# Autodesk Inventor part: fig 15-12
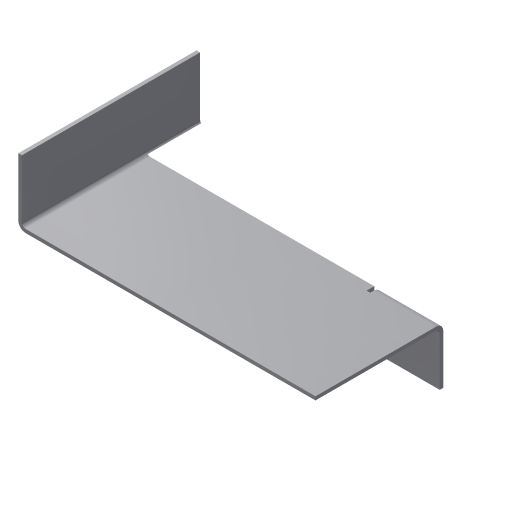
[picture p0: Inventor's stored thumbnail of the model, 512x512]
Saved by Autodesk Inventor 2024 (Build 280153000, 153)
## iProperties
Shininess: 77.0
Angle Display Precision: 2
Document Length Units: 11269
Document Angle Units: 11279
Document Time Units: 11290
Document Mass Units: 11283
Document Length Units Precision: 3
Document Angle Units Precision: 2
Created: 2002-04
Part Number: fig 15-12
Material: Aluminum-6061
Document SubType Name: Sheet Metal
Density: 1 g/cm^3
Sheet Metal Rule: Default
Appearance: Aluminum - Flat-1
Density: 0.0
Volumn: 0.0
Area: 0.0
PropertySet Name: Model Information
Control State: 0
Master: False
Checked Out: False
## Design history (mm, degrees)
node "Face1"
  sketch "Sketch1"
    geometry: L1 (-49.559, 19.574)-(-49.559, -30.426); L2 (-49.559, -30.426)-(50.441, -30.426); L3 (50.441, -30.426)-(50.441, 19.574); L4 (50.441, 19.574)-(32.941, 19.574); L5 (32.941, 19.574)-(32.941, 4.574); L6 (32.941, 4.574)-(-32.059, 4.574); L7 (-32.059, 4.574)-(-32.059, 19.574); L8 (-32.059, 19.574)-(-49.559, 19.574)
    constraints: 16 end point, 6 parallel, 2 equal length, 1 perpendicular, 1 vertical
    dimensions: "d0" = 100 distance of L1.end L2.end; "d1" = 65 distance of L5.end L6.end; "d2" = 15 distance of L6.end L7.end; "d3" = 50 distance of L1.start L1.end
feature "Fold2" dims "d8" = 1 (= BendRadius), "d9" = 90 deg, "d10" = 1 (= BendRadius), "d14" = 1 (= BendReliefWidth), "d15" = 0.5 (= BendReliefDepth), "d16" = 2 (= MinimumRemnant), "d20" = 1 (= Thickness), "SeamGap" = 0.01
feature "Fold3" dims "d11" = 1 (= BendRadius), "d12" = 90 deg, "d13" = 1, "d17" = 1 (= BendReliefWidth), "d18" = 1, "d19" = 2 (= MinimumRemnant), "d20" = 1 (= Thickness), "SeamGap" = 0.01
body "Solid1"
sketch "Sketch2"
  geometry: L1 (100, 0)-(0, 0) reference; L2 (17.5, 50)-(17.5, 35) reference; L3 (82.5, 50)-(82.5, 0)
  constraints: 2 end point, 1 parallel, 1 point on line
face "Plate1" dims "d20" = 1 (= Thickness)
sketch "Sketch3"
  geometry: L1 (81.369, -50)-(0, -50) reference; L2 (17.5, 0)-(17.5, -50)
  constraints: 2 end point, 1 perpendicular, 1 point on line
sketch "Sketch4"
  geometry: L1 (17.5, 0)-(17.5, -50) reference; L2 (-63.869, -15)-(0, -15) reference; L3 (0, -15)-(17.5, -15)
  constraints: 2 end point, 1 collinear, 1 point on line
other parameters: "Thickness" = 1, "BendRadius" = 1 (= Thickness), "BendReliefWidth" = 1 (= Thickness), "BendReliefDepth" = 0.5 (= 0.5 x Thickness), "CornerReliefSize" = 4 (= 4 x Thickness), "MinimumRemnant" = 2 (= 2 x Thickness), "TransitionRadius" = 1 (= BendRadius), "d4" = 1 (= BendRadius), "JacobiRadiusSize" = 1 (= Thickness), "GapSize" = 1 (= Thickness)
